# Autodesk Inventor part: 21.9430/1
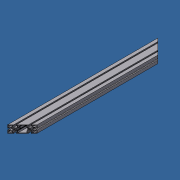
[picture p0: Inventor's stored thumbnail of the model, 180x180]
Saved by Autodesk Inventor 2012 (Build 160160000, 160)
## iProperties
Created: 2013-10
Part Number: 21.9430/1
Material: Aluminum-6061
Description: MILL TO PRINT 21.9430/1
Document SubType Name: Modeling
Designer: Admin
Density: 2.71 g/cm^3
Vendor: F
Stock Number: 20.1032 PROFILE 45X90 F
FINISH: CLEAR ANODIZED
Author: Admin
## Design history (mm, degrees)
sketch "Sketch1"
  geometry: L1 (43, -8.8)-(43, -15.5) reference; L2 (38, -20.5)-(31.3, -20.5) reference; L3 (31.3, -20.5)-(31.3, -13.8) reference; L4 (36.3, -8.8)-(43, -8.8) reference; L5 (-43, 8.8)-(-43, 15.5) reference; L6 (-38, 20.5)-(-31.3, 20.5) reference; L7 (-31.3, 20.5)-(-31.3, 13.8) reference; L8 (-36.3, 8.8)-(-43, 8.8) reference; L9 (43, 15.5)-(43, 8.8) reference; L10 (43, 8.8)-(36.3, 8.8) reference; L11 (31.3, 13.8)-(31.3, 20.5) reference; L12 (31.3, 20.5)-(38, 20.5) reference; L13 (-43, -15.5)-(-43, -8.8) reference; L14 (-43, -8.8)-(-36.3, -8.8) reference; L15 (-31.3, -13.8)-(-31.3, -20.5) reference; L16 (-31.3, -20.5)-(-38, -20.5) reference; L17 (-25.682, -4.596)-(-27.096, -3.182) reference; L18 (-27.096, -3.182)-(-25.763, -1.849) reference; L19 (-25.763, 1.849)-(-27.096, 3.182) reference; L20 (-27.096, 3.182)-(-25.682, 4.596) reference; L21 (-25.682, 4.596)-(-24.349, 3.263) reference; L22 (-20.651, 3.263)-(-19.318, 4.596) reference; L23 (-19.318, 4.596)-(-17.904, 3.182) reference; L24 (-17.904, 3.182)-(-19.237, 1.849) reference; L25 (-19.237, -1.849)-(-17.904, -3.182) reference; L26 (-17.904, -3.182)-(-19.318, -4.596) reference; L27 (-19.318, -4.596)-(-20.651, -3.263) reference; L28 (-24.349, -3.263)-(-25.682, -4.596) reference; L29 (19.318, -4.596)-(17.904, -3.182) reference; L30 (17.904, -3.182)-(19.237, -1.849) reference; L31 (19.237, 1.849)-(17.904, 3.182) reference; L32 (17.904, 3.182)-(19.318, 4.596) reference; L33 (19.318, 4.596)-(20.651, 3.263) reference; L34 (24.349, 3.263)-(25.682, 4.596) reference; L35 (25.682, 4.596)-(27.096, 3.182) reference; L36 (27.096, 3.182)-(25.763, 1.849) reference; L37 (25.763, -1.849)-(27.096, -3.182) reference; L38 (27.096, -3.182)-(25.682, -4.596) reference; L39 (25.682, -4.596)-(24.349, -3.263) reference; L40 (20.651, -3.263)-(19.318, -4.596) reference; L41 (-14.286, -7.786)-(-14.914, -7.157) reference; L42 (-15.5, -5.743)-(-15.5, 5.743) reference; L43 (-14.914, 7.157)-(-14.286, 7.786) reference; L44 (-13.7, 9.2)-(-13.7, 20.5) reference; L45 (-13.7, 20.5)-(13.7, 20.5) reference; L46 (13.7, 20.5)-(13.7, 9.2) reference; L47 (14.286, 7.786)-(14.914, 7.157) reference; L48 (15.5, 5.743)-(15.5, -5.743) reference; L49 (14.914, -7.157)-(14.286, -7.786) reference; L50 (13.7, -9.2)-(13.7, -20.5) reference; L51 (13.7, -20.5)-(-13.7, -20.5) reference; L52 (-13.7, -20.5)-(-13.7, -9.2) reference; L53 (26.6, 22.5)-(26.6, 18) reference; L54 (29.3, 18)-(29.3, 9.5) reference; L55 (29.3, 9.5)-(27, 7.2) reference; L56 (27, 7.2)-(18, 7.2) reference; L57 (18, 7.2)-(15.7, 9.5) reference; L58 (15.7, 9.5)-(15.7, 18) reference; L59 (15.7, 18)-(17.9, 18) reference; L60 (18.4, 18)-(18.4, 22.5) reference; L61 (-18.4, 22.5)-(-18.4, 18) reference; L62 (-15.7, 18)-(-15.7, 9.5) reference; L63 (-15.7, 9.5)-(-18, 7.2) reference; L64 (-18, 7.2)-(-27, 7.2) reference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; A1 r 5 centre (38, -15.5) between (38, -20.5) and (43, -15.5) reference; A2 r 5 centre (36.3, -13.8) between (36.3, -8.8) and (31.3, -13.8) reference; A3 r 5 centre (-38, 15.5) between (-38, 20.5) and (-43, 15.5) reference; A4 r 5 centre (-36.3, 13.8) between (-36.3, 8.8) and (-31.3, 13.8) reference; A5 r 5 centre (36.3, 13.8) between (31.3, 13.8) and (36.3, 8.8) reference; A6 r 5 centre (38, 15.5) between (43, 15.5) and (38, 20.5) reference; A7 r 5 centre (-36.3, -13.8) between (-31.3, -13.8) and (-36.3, -8.8) reference; A8 r 5 centre (-38, -15.5) between (-43, -15.5) and (-38, -20.5) reference; A9 r 3.75 centre (-22.5, 0) between (-24.16, -3.362) and (-20.84, -3.362) reference; A10 r 3.75 centre (22.5, 0) between (25.862, -1.66) and (25.862, 1.66) reference; A11 r 2 centre (-15.7, -9.2) between (-13.7, -9.2) and (-14.286, -7.786) reference; A12 r 2 centre (-13.5, -5.743) between (-15.5, -5.743) and (-14.914, -7.157) reference; A13 r 2 centre (-13.5, 5.743) between (-14.914, 7.157) and (-15.5, 5.743) reference; A14 r 2 centre (-15.7, 9.2) between (-14.286, 7.786) and (-13.7, 9.2) reference; A15 r 2 centre (15.7, 9.2) between (13.7, 9.2) and (14.286, 7.786) reference; A16 r 2 centre (13.5, 5.743) between (15.5, 5.743) and (14.914, 7.157) reference; A17 r 2 centre (13.5, -5.743) between (14.914, -7.157) and (15.5, -5.743) reference; A18 r 2 centre (15.7, -9.2) between (14.286, -7.786) and (13.7, -9.2) reference; A19 r 3.75 centre (-22.5, 0) between (-25.763, 1.849) and (-25.862, 1.66) reference; A20 r 3.75 centre (-22.5, 0) between (-25.862, 1.66) and (-25.763, -1.849) reference; A21 r 3.75 centre (-22.5, 0) between (-24.349, -3.263) and (-24.16, -3.362) reference; A22 r 3.75 centre (-22.5, 0) between (-19.138, 1.66) and (-19.237, 1.849) reference; A23 r 3.75 centre (-22.5, 0) between (-20.651, 3.263) and (-24.349, 3.263) reference; A24 r 3.75 centre (-22.5, 0) between (-20.84, -3.362) and (-20.651, -3.263) reference; A25 r 3.75 centre (-22.5, 0) between (-19.237, -1.849) and (-19.138, 1.66) reference; A26 r 3.75 centre (22.5, 0) between (20.84, 3.362) and (20.651, 3.263) reference; A27 r 3.75 centre (22.5, 0) between (19.237, 1.849) and (19.237, -1.849) reference; A28 r 3.75 centre (22.5, 0) between (20.651, -3.263) and (20.84, -3.362) reference; A29 r 3.75 centre (22.5, 0) between (20.84, -3.362) and (24.349, -3.263) reference; A30 r 3.75 centre (22.5, 0) between (25.763, -1.849) and (25.862, -1.66) reference; A31 r 3.75 centre (22.5, 0) between (25.862, 1.66) and (25.763, 1.849) reference; A32 r 3.75 centre (22.5, 0) between (24.349, 3.263) and (20.84, 3.362) reference
  constraints: 258 end point, 64 point on circle, 40 horizontal, 37 vertical, 32 centre point, 2 point on line, 269 other
extrude "Extrusion1" new body sketch "Sketch1" stored distance "d0" = 914.4; taper "d1" = 0 deg
sketch "Sketch2"
  geometry: L1 (-26.6, 914.4)-(-26.6, 0) reference; L2 (63.4, 914.4)-(63.4, 0) reference; L3 (-26.6, 0)-(63.4, 90); L4 (63.4, 90)-(63.4, 0); L5 (63.4, 0)-(-26.6, 0); 1 further point
  constraints: 6 end point, 1 collinear, 1 perpendicular, 1 point on line
  dimensions: "d2" = 45 deg angle of L5 L3
extrude "Extrusion2" cut sketch "Sketch2" distance "d3" = 609.6; taper "d4" = 0 deg
sketch "Sketch3"
  geometry: L1 (26.022, 0)-(0, 0) reference; L2 (89.661, 0)-(37.618, 0) reference; L3 (0, 26.6)-(0, 45) reference; 3 further points
  dimensions: "d5" = 22.5 distance from line of point (52.07, 22.5) L1; "d6" = 22.5 distance from line of point (115.824, 22.5) L2; "d7" = 52.07 distance from line of point (52.07, 22.5) L3; "d8" = 115.824 distance from line of point (115.824, 22.5) L3
hole "Hole1" sketch "Sketch3" at (52.07, 22.5), (115.824, 22.5) diameter "d9" = 8.5; stored, may be unused: countersink angle "d13" = 82 deg, drill point angle "d15" = 118 deg; dims "d10" = 19.05, "d11" = 9.525, "d12" = 6.35, "d14" = 25.4
workplane "Work Plane1"
sketch "Sketch4"
  geometry: C1 r 4.25 at (52.07, 22.5) reference; C2 r 4.25 at (115.824, 22.5) reference; C3 r 6.5 at (115.824, 22.5); C4 r 6.5 at (52.07, 22.5); 1 further point
  constraints: 2 centre point, 2 coincident
  dimensions: "d17" = 13 diameter of C4; "d18" = 13 diameter of C3
extrude "Extrusion3" cut sketch "Sketch4" distance "d19" = 609.6; taper "d20" = 0 deg
mirror "Mirror1"
body "Solid1"
other parameters: "d16" = -21.59
